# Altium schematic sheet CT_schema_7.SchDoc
size 403 x 220 mm
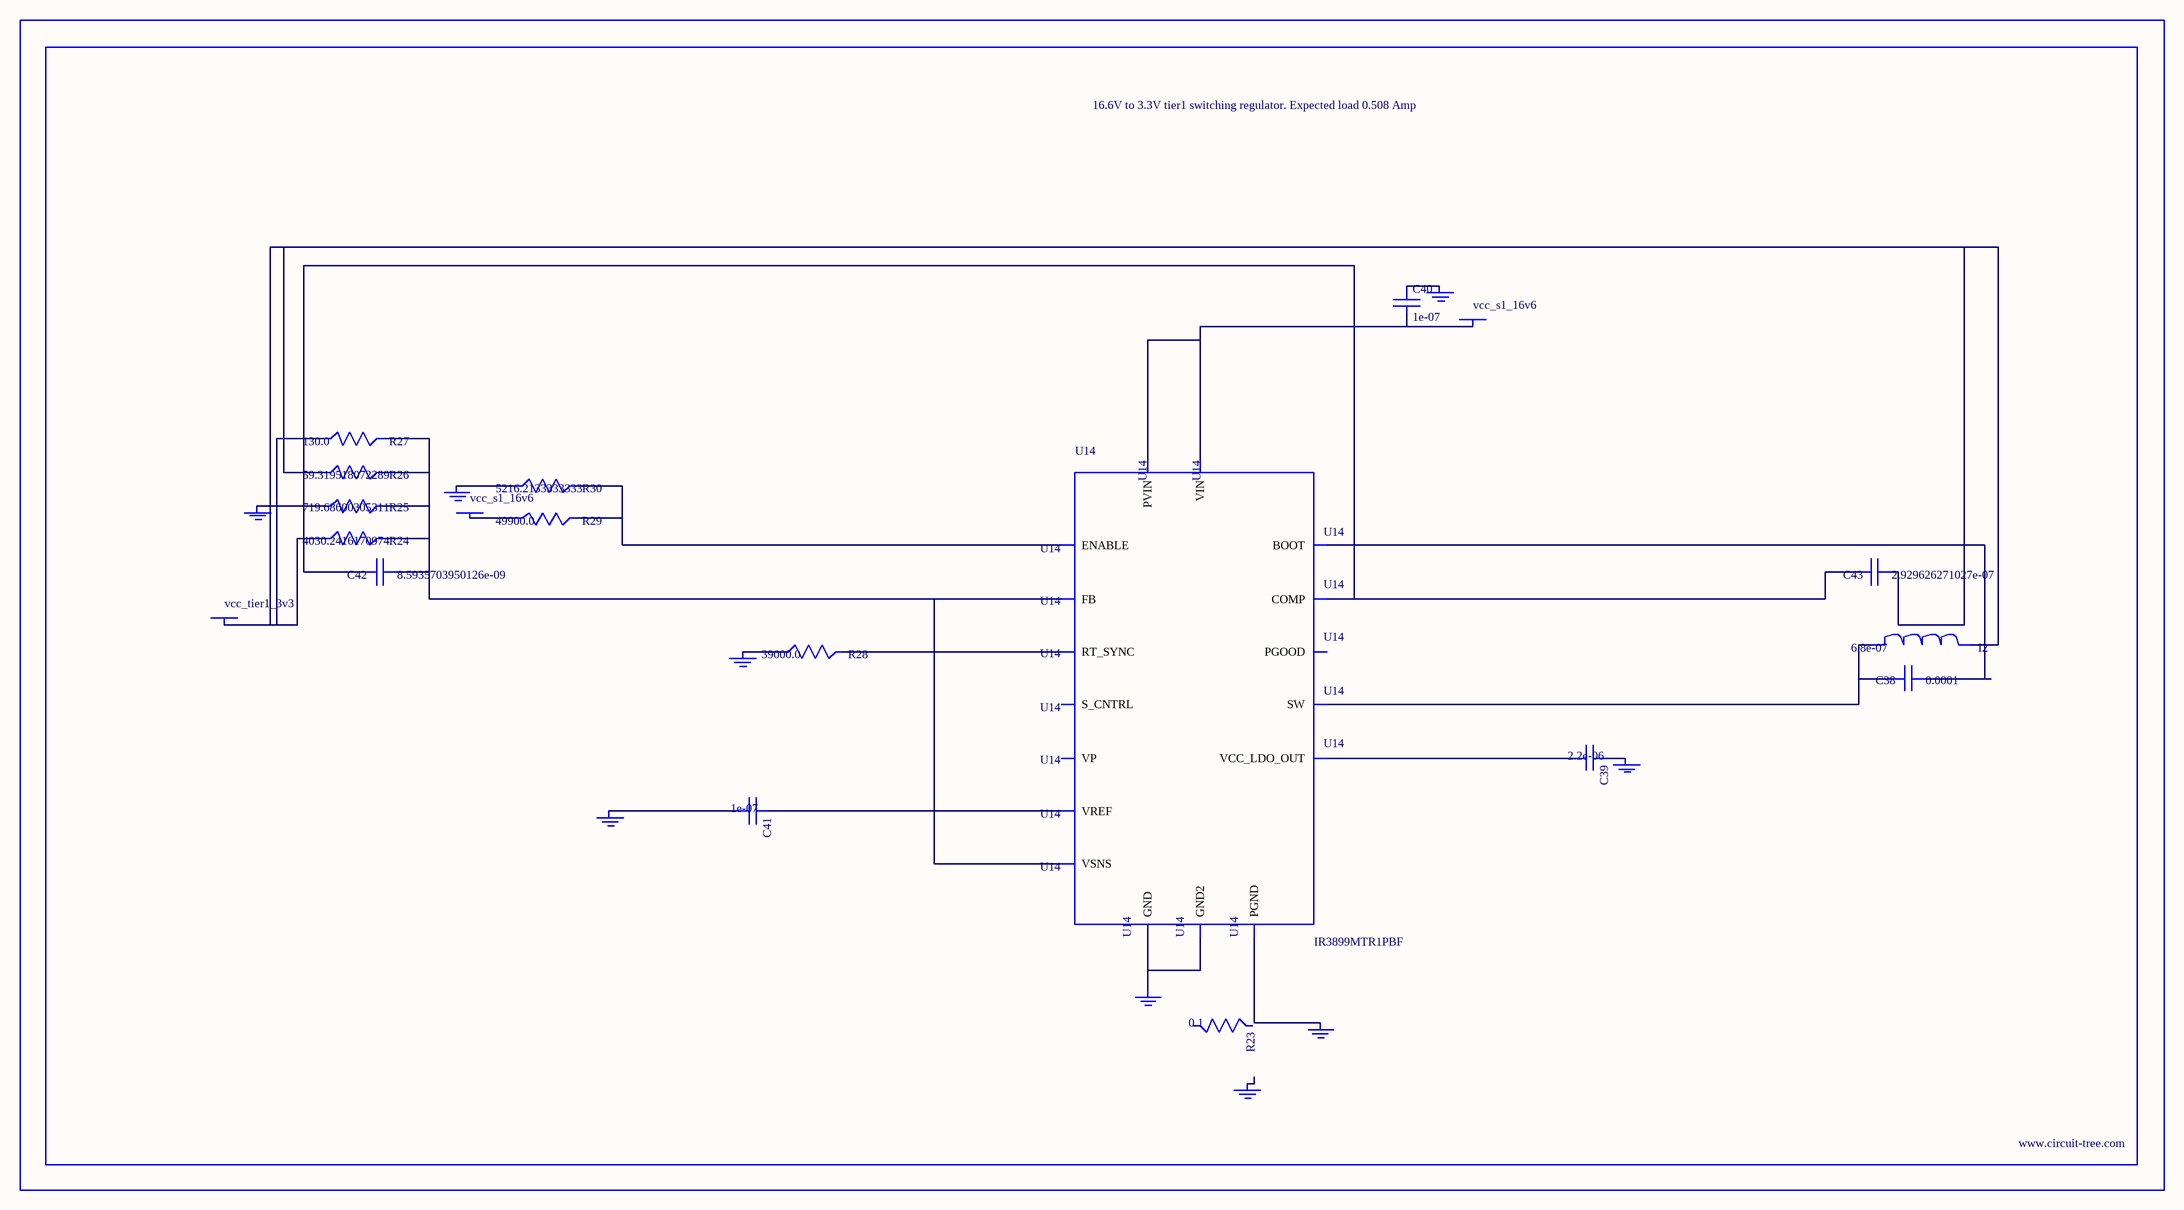
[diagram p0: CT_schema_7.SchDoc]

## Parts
BORDER6  (no value)
C38  0.0001  [C1210]
C39  2.2e-06  [C0603]
C40  1e-07  [C0402]
C41  1e-07  [C0402]
C42  8.5935703950126e-09  [R0603]
C43  2.929626271027e-07  [R0603]
GND_INSTANCE_6_0  (no value)
GND_INSTANCE_6_1  (no value)
GND_INSTANCE_6_2  (no value)
GND_INSTANCE_6_3  (no value)
GND_INSTANCE_6_4  (no value)
GND_INSTANCE_6_5  (no value)
GND_INSTANCE_6_6  (no value)
GND_INSTANCE_6_7  (no value)
GND_INSTANCE_6_8  (no value)
I2  6.8e-07  [IND25X25CZ]
POWER_INSTANCE_6_0  vcc_s1_16v6
POWER_INSTANCE_6_1  vcc_s1_16v6
POWER_INSTANCE_6_2  vcc_tier1_3v3
R23  0.1  [R0603]
R24  4030.2416170974  [R0603]
R25  719.68600305311  [R0603]
R26  59.319518072289  [R0603]
R27  130.0  [R0603]
R28  39000.0  [R0603]
R29  49900.0  [R0603]
R30  5216.2133333333  [R0603]
U14  IR3899MTR1PBF  [IR3899MTR1PBF]

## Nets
NetC38_1: C38.1 U14.14(BOOT)
NetC38_2: C38.2 I2.1 U14.12(SW)
NetC39_1: C39.1 GND_INSTANCE_6_4.0(GND)
NetC39_2: C39.2 U14.10(VCC_LDO_OUT)
NetC40_1: C40.1 GND_INSTANCE_6_3.0(GND)
NetC40_2: C40.2 POWER_INSTANCE_6_0.0(PWR) U14.9(VIN) U14.13(PVIN)
NetC41_1: C41.1 U14.2(VREF)
NetC41_2: C41.2 GND_INSTANCE_6_1.0(GND)
NetC42_1: C42.1 R24.2 R25.2 R26.2 R27.2 U14.1(FB) U14.8(VSNS)
NetC42_2: C42.2 C43.2 U14.3(COMP)
NetC43_1: C43.1 I2.2 POWER_INSTANCE_6_2.0(PWR) R24.1 R26.1 R27.1
NetGND_INSTANCE_6_0_0: GND_INSTANCE_6_0.0(GND) R25.1
NetGND_INSTANCE_6_2_0: GND_INSTANCE_6_2.0(GND) R28.1
NetGND_INSTANCE_6_6_0: GND_INSTANCE_6_6.0(GND) U14.11(PGND)
NetGND_INSTANCE_6_7_0: GND_INSTANCE_6_7.0(GND) R30.1
NetGND_INSTANCE_6_8_0: GND_INSTANCE_6_8.0(GND) U14.4(GND) U14.17(GND2)
NetPOWER_INSTANCE_6_1_0: POWER_INSTANCE_6_1.0(PWR) R29.1
NetR28_2: R28.2 U14.5(RT_SYNC)
NetR29_2: R29.2 R30.2 U14.15(ENABLE)

Not connected (* = marked no-connect by the designer): GND_INSTANCE_6_5 0(GND); R23 1 2; U14 6(S_CNTRL) 7(PGOOD) 16(VP)

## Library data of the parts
BORDER6 = BORDER_PAGE6
C38 = GRM32ER61A107ME20L
C39 = C0603C225K8RACTU
C40 C41 = C0402C104K3RACTU
C42 = C42
C43 = C43
GND_INSTANCE_6_0-GND_INSTANCE_6_8 = GND
I2 = IHLP2525CZERR68M01
POWER_INSTANCE_6_0-POWER_INSTANCE_6_2 = PWR
R23 = ERJ-3RSFR10V
R24 = R24
R25 = R25
R26 = R26
R27 = RC0603JR-07130RL
R28 = RC0603JR-0739KL
R29 = RC0603FR-0749K9
R30 = R30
